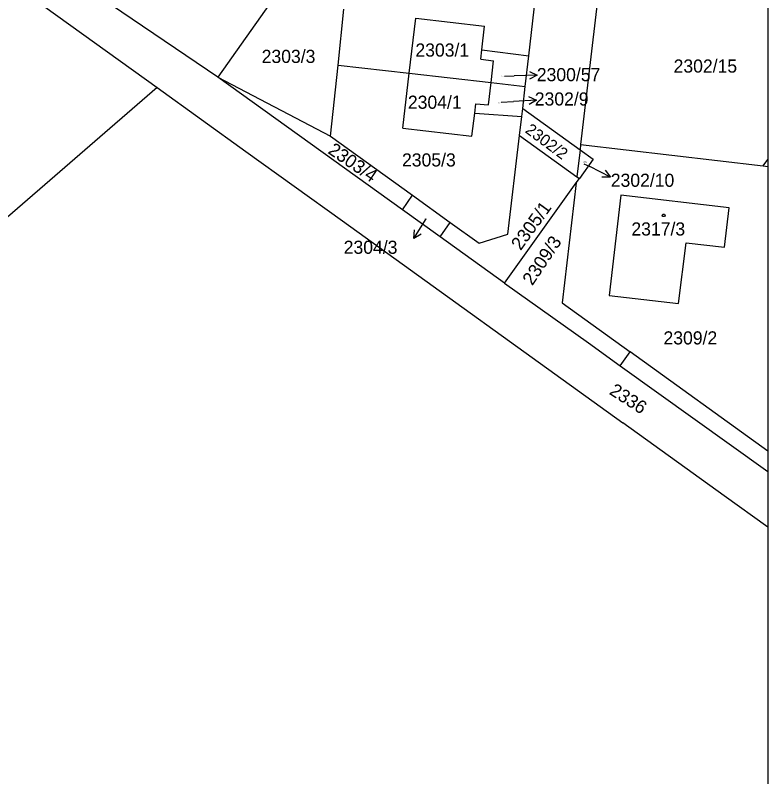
# Model space of a CAD drawing. Extents: x -639590 to -639298, y -1193269 to -1192863.
# Drawn here: x -639395.8 to -639298.4, y -1193132.4 to -1193033.8 of the extents above; entities that cross this region are included whole.
import ezdxf

# ---------------------------------------------------------------- set-up
doc = ezdxf.new("R2010")
doc.units = 0
for name, color, linetype in [('Vrstva 1', 7, 'Continuous'), ('Vrstva 2', 7, 'Continuous'), ('Vrstva 5', 7, 'Continuous'), ('Vrstva 61', 7, 'Continuous'), ('Vrstva 7', 7, 'Continuous')]:
    doc.layers.add(name, color=color, linetype=linetype)

msp = doc.modelspace()

# ---------------------------------------------------------------- linework, layer by layer
at = {"layer": 'Vrstva 1'}
for p, q in [((-639319.4, -1193023.24), (-639322.6, -1193050.55)), ((-639359.93, -1193028.23), (-639369.56, -1193041.81)), ((-639369.56, -1193041.81), (-639388.01, -1193029.3)), ((-639394.21, -1193031.06), (-639377.41, -1193043.16)), ((-639329.3, -1193039.04), (-639328.4, -1193031.29)), ((-639353.99, -1193040.25), (-639353.23, -1193033.04)), ((-639344.78, -1193041.31), (-639343.94, -1193034.19)), ((-639343.94, -1193034.19), (-639335.02, -1193035.22)), ((-639335.37, -1193038.3), (-639335.02, -1193035.22)), ((-639335.51, -1193039.49), (-639335.37, -1193038.3)), ((-639335.37, -1193038.3), (-639329.3, -1193039.04)), ((-639329.77, -1193043.04), (-639329.3, -1193039.04)), ((-639354.96, -1193049.46), (-639353.99, -1193040.25)), ((-639353.99, -1193040.25), (-639344.78, -1193041.31)), ((-639335.51, -1193039.49), (-639333.88, -1193039.69)), ((-639334.2, -1193042.53), (-639333.88, -1193039.69)), ((-639345.61, -1193048.44), (-639344.78, -1193041.31)), ((-639344.78, -1193041.31), (-639334.2, -1193042.53)), ((-639369.56, -1193041.81), (-639354.96, -1193049.46)), ((-639345.66, -1193058.97), (-639369.56, -1193041.81)), ((-639377.41, -1193043.16), (-639466.59, -1193120.49)), ((-639377.41, -1193043.16), (-639365.92, -1193051.43)), ((-639334.52, -1193045.38), (-639334.2, -1193042.53)), ((-639334.2, -1193042.53), (-639329.77, -1193043.04)), ((-639330.1, -1193045.89), (-639329.77, -1193043.04)), ((-639336.3, -1193046.46), (-639336.16, -1193045.27)), ((-639336.16, -1193045.27), (-639334.52, -1193045.38)), ((-639330.22, -1193046.89), (-639330.1, -1193045.89)), ((-639330.1, -1193045.89), (-639322.68, -1193051.24)), ((-639336.67, -1193049.45), (-639336.3, -1193046.46)), ((-639336.3, -1193046.46), (-639330.22, -1193046.89)), ((-639330.51, -1193049.36), (-639330.22, -1193046.89)), ((-639345.61, -1193048.44), (-639336.67, -1193049.45)), ((-639354.96, -1193049.46), (-639344.34, -1193057.11)), ((-639332.01, -1193062.15), (-639330.51, -1193049.36)), ((-639330.51, -1193049.36), (-639323.08, -1193054.7)), ((-639322.6, -1193050.55), (-639322.68, -1193051.24)), ((-639322.6, -1193050.55), (-639299, -1193053.31)), ((-639365.92, -1193051.43), (-639353.43, -1193060.43)), ((-639322.68, -1193051.24), (-639323.08, -1193054.7)), ((-639322.68, -1193051.24), (-639321, -1193052.44)), ((-639321, -1193052.44), (-639322.77, -1193054.92)), ((-639299, -1193053.31), (-639298.391, -1193052.458)), ((-639299, -1193053.31), (-639298.391, -1193053.381)), ((-639323.17, -1193055.48), (-639322.77, -1193054.92)), ((-639323.08, -1193054.7), (-639322.77, -1193054.92)), ((-639332.45, -1193068.46), (-639323.17, -1193055.48)), ((-639323.17, -1193055.48), (-639325, -1193071.04)), ((-639345.66, -1193058.97), (-639344.34, -1193057.11)), ((-639344.34, -1193057.11), (-639339.48, -1193060.62)), ((-639317.39, -1193057.1), (-639318.92, -1193070.08)), ((-639303.37, -1193058.74), (-639317.39, -1193057.1)), ((-639340.79, -1193062.47), (-639345.66, -1193058.97)), ((-639303.99, -1193063.83), (-639303.37, -1193058.74)), ((-639353.43, -1193060.43), (-639317.16, -1193086.55)), ((-639340.79, -1193062.47), (-639339.48, -1193060.62)), ((-639339.48, -1193060.62), (-639335.73, -1193063.31)), ((-639332.45, -1193068.46), (-639340.79, -1193062.47)), ((-639335.73, -1193063.31), (-639332.01, -1193062.15)), ((-639309.94, -1193071.13), (-639308.93, -1193063.26)), ((-639308.93, -1193063.26), (-639303.99, -1193063.83)), ((-639332.45, -1193068.46), (-639321.59, -1193076.22)), ((-639318.92, -1193070.08), (-639309.94, -1193071.13)), ((-639325, -1193071.04), (-639316.2, -1193077.38)), ((-639321.59, -1193076.22), (-639317.48, -1193079.17)), ((-639317.48, -1193079.17), (-639316.2, -1193077.38)), ((-639298.391, -1193090.201), (-639316.2, -1193077.38)), ((-639317.48, -1193079.17), (-639298.391, -1193092.864)), ((-639304.03, -1193096), (-639317.16, -1193086.55)), ((-639298.391, -1193100.062), (-639304.03, -1193096))]:
    msp.add_line(p, q, dxfattribs=at)
at = {"layer": 'Vrstva 5'}
msp.add_lwpolyline([(-639311.77, -1193059.57), (-639311.68, -1193059.72), (-639311.77, -1193059.87), (-639311.95, -1193059.87), (-639312.04, -1193059.72), (-639311.95, -1193059.57)], close=True, dxfattribs=at)
at = {"layer": 'Vrstva 61'}
msp.add_lwpolyline([(-639298.391, -1192863.27), (-639298.391, -1193268.77)], dxfattribs=at)
at = {"layer": 'Vrstva 7'}
for p, q in [((-639332.41, -1193041.67), (-639331.22, -1193041.64)), ((-639328.221, -1193041.551), (-639331.22, -1193041.64)), ((-639332.87, -1193045.04), (-639331.3, -1193044.95)), ((-639328.304, -1193044.786), (-639331.3, -1193044.95)), ((-639322.18, -1193053.03), (-639321.43, -1193053.4)), ((-639318.746, -1193054.741), (-639321.43, -1193053.4)), ((-639344.2, -1193062.701), (-639342.59, -1193060.17))]:
    msp.add_line(p, q, dxfattribs=at)
for points in [[(-639329.236, -1193041.081), (-639328.221, -1193041.551), (-639329.206, -1193042.081)], [(-639329.33, -1193044.342), (-639328.304, -1193044.786), (-639329.276, -1193045.34)], [(-639319.417, -1193053.847), (-639318.746, -1193054.741), (-639319.864, -1193054.741)], [(-639343.242, -1193062.126), (-639344.2, -1193062.701), (-639344.085, -1193061.589)]]:
    msp.add_lwpolyline(points, dxfattribs=at)

# ---------------------------------------------------------------- texts
at = {"layer": 'Vrstva 2'}
for s, height, p in [('2303/1', 1.7, (-639343.979, -1193039.16)), ('2303/3', 1.7, (-639363.873, -1193039.98)), ('2302/15', 1.7, (-639310.573, -1193041.23)), ('2300/57', 0.1, (-639332.856, -1193041.71)), ('2304/1', 1.7, (-639344.952, -1193045.91)), ('2302/9', 0.1, (-639333.356, -1193045.2)), ('2305/3', 1.7, (-639345.713, -1193053.38)), ('2302/10', 0.1, (-639322.256, -1193052.83)), ('2304/3', 0.1, (-639342.836, -1193060.15)), ('2317/3', 1.7, (-639316.033, -1193062.31)), ('2309/2', 1.7, (-639311.883, -1193076.41))]:
    msp.add_text(s, height=height, dxfattribs=at).set_placement(p)
for s, height, rotation, p in [('2302/2', 1.5, 323.26279, (-639329.892, -1193048.895)), ('2303/4', 1.7, 325.72651, (-639355.414, -1193051.594)), ('2305/1', 1.7, 54.14451, (-639330.361, -1193064.338)), ('2309/3', 1.7, 56.20716, (-639328.848, -1193068.883)), ('2336', 1.7, 327.27349, (-639319.01, -1193082.768))]:
    msp.add_text(s, height=height, rotation=rotation, dxfattribs=at).set_placement(p)
at = {"layer": 'Vrstva 7'}
for s, p in [('2300/57', (-639328.273, -1193042.34)), ('2302/9', (-639328.534, -1193045.49)), ('2302/10', (-639318.702, -1193056.01)), ('2304/3', (-639353.257, -1193064.68))]:
    msp.add_text(s, height=1.7, dxfattribs=at).set_placement(p)

doc.saveas('drawing.dxf')
